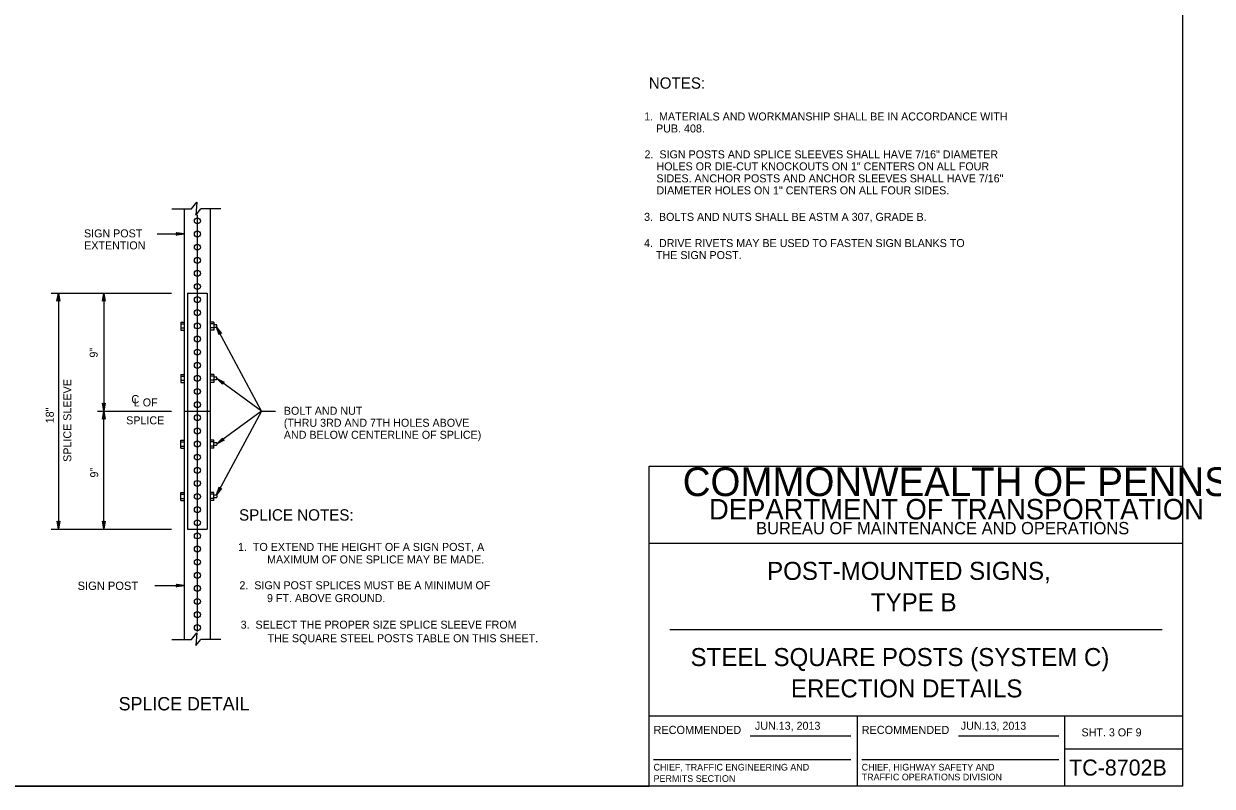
# Model space of a CAD drawing. Extents: x 644358 to 648627, y 294594 to 295782.
# Drawn here: x 646431.9 to 646877.4, y 295202.6 to 295488.4 of the extents above; entities that cross this region are included whole.
import ezdxf

# ---------------------------------------------------------------- set-up
doc = ezdxf.new("R2010")
doc.units = 0
for name, color, linetype in [('1', 7, 'Continuous'), ('2', 7, 'Continuous'), ('3', 7, 'Continuous'), ('4', 7, 'Continuous')]:
    doc.layers.add(name, color=color, linetype=linetype)

# ---------------------------------------------------------------- blocks, each defined once
blk = doc.blocks.new('RARROW')
at = {"layer": '3'}
blk.add_lwpolyline([(-2.2695, 0.285), (-2.184875, 0.12075), (0, 0), (-2.2695, 0.285), (-2.38575, 0.384625), (0, 0), (-2.183125, -0.108), (-2.262875, -0.2705), (0, 0), (-2.38575, -0.379125), (-2.262875, -0.2705)], dxfattribs=at)

msp = doc.modelspace()

# ---------------------------------------------------------------- linework, layer by layer
at = {"layer": '1'}
for p, q in [((646866.31, 295202.63), (646866.31, 295766.63)), ((646666.31, 295202.63), (646666.31, 295322.63)), ((646666.31, 295322.63), (646866.31, 295322.63)), ((646866.31, 295293.63), (646666.31, 295293.63)), ((646674.06, 295261.31), (646858.56, 295261.31)), ((646666.31, 295229), (646866.31, 295229)), ((646744.31, 295229), (646744.31, 295202.63)), ((646822.19, 295202.63), (646822.19, 295229)), ((646704.24, 295221.57), (646741.87, 295221.57)), ((646782.24, 295221.57), (646819.87, 295221.57)), ((646822.19, 295216.63), (646866.31, 295216.63)), ((646667.99, 295212.68), (646741.87, 295212.68)), ((646745.99, 295212.68), (646819.87, 295212.68)), ((646866.31, 295202.63), (646080.31, 295202.63)), ((646080.31, 295202.63), (646666.31, 295202.63))]:
    msp.add_line(p, q, dxfattribs=at)
at = {"layer": '2'}
for p, q in [((646494.83, 295419.07), (646496.83, 295421.57)), ((646496.83, 295421.57), (646496.45, 295416.69)), ((646487.45, 295419.07), (646494.83, 295419.07)), ((646492.08, 295419.07), (646492.08, 295343.19)), ((646496.45, 295416.69), (646498.33, 295419.07)), ((646496.95, 295416.82), (646496.95, 295260.57)), ((646505.83, 295419.07), (646498.33, 295419.07)), ((646501.95, 295343.19), (646501.95, 295419.07)), ((646496.95, 295414.44), (646496.95, 295414.44)), ((646496.95, 295409.57), (646496.95, 295409.57)), ((646496.95, 295404.69), (646496.95, 295404.69)), ((646496.95, 295399.69), (646496.95, 295399.69)), ((646496.95, 295394.82), (646496.95, 295394.82)), ((646496.95, 295389.94), (646496.95, 295389.94)), ((646493.33, 295387.41), (646500.7, 295387.41)), ((646493.33, 295387.41), (646493.33, 295298.94)), ((646500.7, 295387.41), (646500.7, 295298.94)), ((646496.95, 295384.94), (646496.95, 295384.94)), ((646490.83, 295376.57), (646490.83, 295373.57)), ((646490.83, 295376.57), (646492.08, 295376.57)), ((646496.95, 295380.07), (646496.95, 295380.07)), ((646503.2, 295376.57), (646501.95, 295376.57)), ((646503.2, 295376.57), (646503.2, 295373.57)), ((646490.83, 295375.95), (646492.08, 295375.95)), ((646490.83, 295374.45), (646492.08, 295374.45)), ((646490.83, 295373.57), (646492.08, 295373.57)), ((646496.95, 295375.19), (646496.95, 295375.19)), ((646503.2, 295375.95), (646501.95, 295375.95)), ((646503.2, 295374.45), (646501.95, 295374.45)), ((646503.2, 295373.57), (646501.95, 295373.57)), ((646503.2, 295375.7), (646504.2, 295375.7)), ((646503.2, 295374.7), (646504.2, 295374.7)), ((646504.33, 295375.45), (646504.2, 295375.7)), ((646504.33, 295374.82), (646504.2, 295374.7)), ((646504.33, 295374.82), (646504.33, 295375.45)), ((646496.95, 295370.19), (646496.95, 295370.19)), ((646496.95, 295365.32), (646496.95, 295365.32)), ((646496.95, 295360.32), (646496.95, 295360.32)), ((646490.83, 295356.9), (646490.83, 295353.9)), ((646490.83, 295356.9), (646492.08, 295356.9)), ((646490.83, 295356.28), (646492.08, 295356.28)), ((646490.83, 295354.78), (646492.08, 295354.78)), ((646496.95, 295355.57), (646496.95, 295355.57)), ((646503.2, 295356.9), (646501.95, 295356.9)), ((646503.2, 295356.28), (646501.95, 295356.28)), ((646503.2, 295354.78), (646501.95, 295354.78)), ((646503.2, 295356.9), (646503.2, 295353.9)), ((646503.2, 295356.03), (646504.2, 295356.03)), ((646503.2, 295355.03), (646504.2, 295355.03)), ((646504.33, 295355.78), (646504.2, 295356.03)), ((646504.33, 295355.15), (646504.2, 295355.03)), ((646504.33, 295355.15), (646504.33, 295355.78)), ((646490.83, 295353.9), (646492.08, 295353.9)), ((646496.95, 295350.57), (646496.95, 295350.57)), ((646503.2, 295353.9), (646501.95, 295353.9)), ((646496.95, 295345.57), (646496.95, 295345.57)), ((646492.08, 295343.19), (646492.08, 295257.57)), ((646492.08, 295343.19), (646501.95, 295343.19)), ((646496.95, 295340.82), (646496.95, 295340.82)), ((646501.95, 295257.57), (646501.95, 295343.19)), ((646490.83, 295329.36), (646490.83, 295332.36)), ((646490.83, 295332.36), (646492.08, 295332.36)), ((646496.95, 295335.82), (646496.95, 295335.82)), ((646503.2, 295332.36), (646501.95, 295332.36)), ((646503.2, 295329.36), (646503.2, 295332.36)), ((646490.83, 295331.74), (646492.08, 295331.74)), ((646490.83, 295330.11), (646492.08, 295330.11)), ((646490.83, 295329.36), (646492.08, 295329.36)), ((646496.95, 295330.82), (646496.95, 295330.82)), ((646503.2, 295331.74), (646501.95, 295331.74)), ((646503.2, 295330.11), (646501.95, 295330.11)), ((646503.2, 295329.36), (646501.95, 295329.36)), ((646503.2, 295331.49), (646504.2, 295331.49)), ((646503.2, 295330.49), (646504.2, 295330.49)), ((646504.33, 295331.24), (646504.2, 295331.49)), ((646504.33, 295330.61), (646504.2, 295330.49)), ((646504.33, 295331.24), (646504.33, 295330.61)), ((646496.95, 295325.94), (646496.95, 295325.94)), ((646496.95, 295321.07), (646496.95, 295321.07)), ((646496.95, 295316.07), (646496.95, 295316.07)), ((646490.83, 295309.69), (646490.83, 295312.69)), ((646490.83, 295312.69), (646492.08, 295312.69)), ((646490.83, 295312.07), (646492.08, 295312.07)), ((646490.83, 295310.44), (646492.08, 295310.44)), ((646490.83, 295309.69), (646492.08, 295309.69)), ((646496.95, 295311.19), (646496.95, 295311.19)), ((646503.2, 295312.69), (646501.95, 295312.69)), ((646503.2, 295312.07), (646501.95, 295312.07)), ((646503.2, 295310.44), (646501.95, 295310.44)), ((646503.2, 295309.69), (646501.95, 295309.69)), ((646503.2, 295309.69), (646503.2, 295312.69)), ((646503.2, 295311.82), (646504.2, 295311.82)), ((646503.2, 295310.82), (646504.2, 295310.82)), ((646504.33, 295311.57), (646504.2, 295311.82)), ((646504.33, 295310.94), (646504.2, 295310.82)), ((646504.33, 295311.57), (646504.33, 295310.94)), ((646496.95, 295306.32), (646496.95, 295306.32)), ((646496.95, 295301.44), (646496.95, 295301.44)), ((646493.33, 295298.94), (646500.7, 295298.94)), ((646496.95, 295296.44), (646496.95, 295296.44)), ((646496.95, 295291.44), (646496.95, 295291.44)), ((646496.95, 295286.69), (646496.95, 295286.69)), ((646496.95, 295281.69), (646496.95, 295281.69)), ((646496.95, 295276.69), (646496.95, 295276.69)), ((646496.95, 295271.82), (646496.95, 295271.82)), ((646496.95, 295266.94), (646496.95, 295266.94)), ((646496.95, 295262.07), (646496.95, 295262.07)), ((646487.45, 295257.57), (646494.83, 295257.57)), ((646494.83, 295257.57), (646496.83, 295260.07)), ((646496.83, 295260.07), (646496.45, 295255.32)), ((646496.45, 295255.32), (646498.33, 295257.57)), ((646505.83, 295257.57), (646498.33, 295257.57))]:
    msp.add_line(p, q, dxfattribs=at)
for centre in [(646497, 295414.52), (646497, 295409.57), (646497, 295404.65), (646497, 295399.73), (646497, 295394.82), (646497, 295389.9), (646497, 295384.95), (646497, 295380.1), (646497, 295375.15), (646497, 295370.23), (646497, 295365.31), (646497, 295360.4), (646497, 295355.48), (646497, 295350.56), (646497, 295345.65), (646497, 295340.73), (646497, 295335.78), (646497, 295330.86), (646497, 295325.94), (646497, 295321.03), (646497, 295316.11), (646497, 295311.19), (646497, 295306.27), (646497, 295301.36), (646497, 295296.44), (646497, 295291.52), (646497, 295286.61), (646497, 295281.69), (646497, 295276.77), (646497, 295271.86), (646497, 295266.94), (646497, 295262.02)]:
    msp.add_circle(centre, 1.12, dxfattribs=at)
at = {"layer": '4'}
for p, q in [((646520.99, 295343.19), (646504.2, 295374.7)), ((646520.99, 295343.19), (646504.33, 295355.47)), ((646496.95, 295343.19), (646501.95, 295343.19)), ((646520.99, 295343.19), (646504.2, 295311.82)), ((646520.99, 295343.19), (646504.33, 295330.92))]:
    msp.add_line(p, q, dxfattribs=at)
for points in [[(646481.87, 295409.64), (646492.08, 295409.64)], [(646442.25, 295387.41), (646487.33, 295387.41)], [(646444.88, 295387.41), (646444.88, 295298.94)], [(646461.95, 295387.41), (646461.95, 295343.19)], [(646459.58, 295343.19), (646487.33, 295343.19)], [(646461.95, 295298.94), (646461.95, 295343.19)], [(646520.99, 295343.19), (646526.25, 295343.19)], [(646442.25, 295298.94), (646487.33, 295298.94)], [(646480.99, 295277.82), (646492.08, 295277.82)]]:
    msp.add_lwpolyline(points, dxfattribs=at)

# ---------------------------------------------------------------- block references
at = {"layer": '2', "xscale": 1.2574347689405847, "yscale": 1.3092961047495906}
for p in [(646492.08, 295409.64), (646492.08, 295277.82)]:
    msp.add_blockref('RARROW', p, dxfattribs=at)
at = {"layer": '2'}
for p, xscale, yscale, rotation in [((646444.88, 295387.41), 1.2574347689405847, 1.3092961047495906, 89.99999999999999), ((646461.95, 295387.41), 1.2574347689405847, 1.3092961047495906, 89.99999999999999), ((646504.2, 295374.7), 1.257434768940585, 1.3092961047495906, 118.6809314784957), ((646504.33, 295355.47), 1.257434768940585, 1.3092961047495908, 144.24684404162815), ((646461.95, 295343.19), 1.2574347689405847, 1.3092961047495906, -90.00000000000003), ((646461.95, 295343.19), 1.2574347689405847, 1.3092961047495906, 89.99999999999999), ((646504.33, 295330.92), 1.2574347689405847, 1.3092961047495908, -143.77483896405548), ((646504.2, 295311.82), 1.2574347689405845, 1.3092961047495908, -117.96802497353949), ((646444.88, 295298.94), 1.2574347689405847, 1.3092961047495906, -90.00000000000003), ((646461.95, 295298.94), 1.2574347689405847, 1.3092961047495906, -90.00000000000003)]:
    msp.add_blockref('RARROW', p, dxfattribs=dict(at, xscale=xscale, yscale=yscale, rotation=rotation))

# ---------------------------------------------------------------- texts
at = {"layer": '1'}
for s, height, p in [('COMMONWEALTH OF PENNSYLVANIA', 10.7828, (646678.9, 295311.36)), ('DEPARTMENT OF TRANSPORTATION', 7.6837, (646688.76, 295302.61)), ('BUREAU OF MAINTENANCE AND OPERATIONS', 4.6253, (646706.41, 295297.04)), ('POST-MOUNTED SIGNS,', 6.75, (646710.54, 295279.97)), ('TYPE B', 6.75, (646749.45, 295268.22)), ('STEEL SQUARE POSTS (SYSTEM C)', 6.75, (646681.84, 295247.66)), ('ERECTION DETAILS', 6.75, (646719.47, 295235.91)), ('RECOMMENDED', 3.048, (646667.99, 295222.2)), ('RECOMMENDED', 3.048, (646745.99, 295222.2)), ('SHT. 3 OF 9', 3, (646828.39, 295221.31)), ('TC-8702B', 6, (646823.77, 295206.63)), ('CHIEF, TRAFFIC ENGINEERING AND', 2.5, (646667.99, 295208.51)), ('TRAFFIC OPERATIONS DIVISION', 2.5, (646745.99, 295204.81)), ('CHIEF, HIGHWAY SAFETY AND', 2.5, (646745.99, 295208.51)), ('PERMITS SECTION', 2.5, (646667.99, 295204.26))]:
    msp.add_text(s, height=height, dxfattribs=at).set_placement(p)
at = {"layer": '2'}
for s, height, p in [('SPLICE DETAIL', 5, (646467.49, 295231.05)), ('JUN.13, 2013', 3, (646705.98, 295223.79)), ('JUN.13, 2013', 3, (646783.14, 295223.79))]:
    msp.add_text(s, height=height, dxfattribs=at).set_placement(p)
at = {"layer": '4'}
for s, height, p in [('NOTES:', 4.25, (646666.18, 295464.04)), ('1.  MATERIALS AND WORKMANSHIP SHALL BE IN ACCORDANCE WITH ', 3, (646664.46, 295452.14)), ('    PUB. 408.', 3, (646664.46, 295447.64)), ('2.  SIGN POSTS AND SPLICE SLEEVES SHALL HAVE 7/16" DIAMETER', 3, (646664.6, 295437.94)), ('    HOLES OR DIE-CUT KNOCKOUTS ON 1" CENTERS ON ALL FOUR', 3, (646664.6, 295433.44)), ('    SIDES. ANCHOR POSTS AND ANCHOR SLEEVES SHALL HAVE 7/16"', 3, (646664.6, 295428.94)), ('    DIAMETER HOLES ON 1" CENTERS ON ALL FOUR SIDES.', 3, (646664.6, 295424.44)), ('3.  BOLTS AND NUTS SHALL BE ASTM A 307, GRADE B.', 3, (646664.43, 295414.51)), ('SIGN POST', 3, (646454.5, 295408.32)), ('4.  DRIVE RIVETS MAY BE USED TO FASTEN SIGN BLANKS TO', 3, (646664.43, 295404.69)), ('EXTENTION', 3, (646454.56, 295403.82)), ('    THE SIGN POST.', 3, (646664.43, 295400.19)), ('C', 3.11, (646472.22, 295346.11)), ('L OF', 3, (646473.17, 295344.97)), ('SPLICE', 3, (646470.31, 295338.25)), ('BOLT AND NUT', 3, (646529.4, 295341.84)), ('(THRU 3RD AND 7TH HOLES ABOVE', 3, (646529.4, 295337.34)), ('AND BELOW CENTERLINE OF SPLICE)', 3, (646529.4, 295332.84)), ('SPLICE NOTES:', 4.25, (646512.62, 295302.18)), ('1.  TO EXTEND THE HEIGHT OF A SIGN POST, A', 3, (646512.23, 295290.81)), (' MAXIMUM OF ONE SPLICE MAY BE MADE.', 3, (646522.01, 295286.12)), ('SIGN POST', 3.115, (646452.11, 295276.19)), ('2.  SIGN POST SPLICES MUST BE A MINIMUM OF', 3, (646512.75, 295276.44)), (' 9 FT. ABOVE GROUND.', 3, (646521.97, 295271.63)), ('3.  SELECT THE PROPER SIZE SPLICE SLEEVE FROM', 3, (646513.2, 295261.68)), (' THE SQUARE STEEL POSTS TABLE ON THIS SHEET.', 3, (646522.18, 295256.59))]:
    msp.add_text(s, height=height, dxfattribs=at).set_placement(p)
for s, p in [('9"', (646459.62, 295363.27)), ('SPLICE SLEEVE', (646449.75, 295324.2)), ('18"', (646443.17, 295338.64)), ('9"', (646459.8, 295318.31))]:
    msp.add_text(s, height=3, rotation=90, dxfattribs=at).set_placement(p)

doc.saveas('drawing.dxf')
